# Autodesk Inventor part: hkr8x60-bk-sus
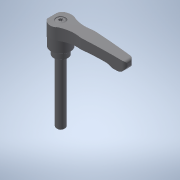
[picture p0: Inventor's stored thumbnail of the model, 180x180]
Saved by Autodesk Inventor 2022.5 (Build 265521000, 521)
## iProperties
Created: 2017-09
Part Number: hkr8x60-bk-sus
Material: 一般
Document SubType Name: Modeling
Designer: imaocorp
Density: 1 g/cm^3
Appearance: 既定
Author: imaocorp
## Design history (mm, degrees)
node "hkr8x60-bk-sus.x_t1"
node "hkr8x60-bk-sus"
node "Base1"
